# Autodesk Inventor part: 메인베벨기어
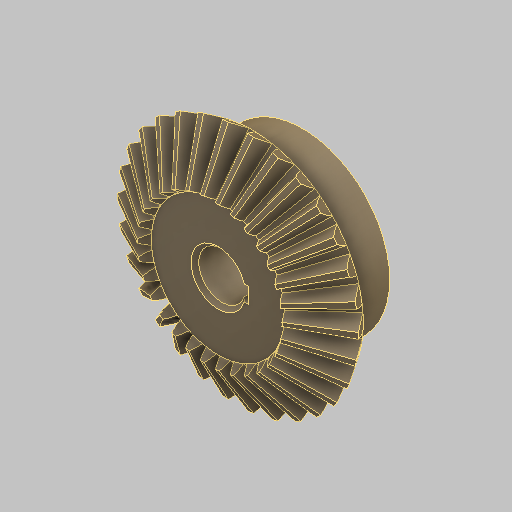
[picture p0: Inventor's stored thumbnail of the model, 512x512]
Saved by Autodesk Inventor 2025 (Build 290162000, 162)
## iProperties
Created: 2024-08
Part Number: 메인베벨기어
Material: 강철, 탄소
Document SubType Name: Modeling
Designer: 현기
Density: 7.87 g/cm^3
Appearance: 기본값
Author: jhkim
Sending System: Autodesk Inventor 2025
Preprocessor: ST-DEVELOPER v20
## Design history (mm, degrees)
feature "Solid1"
node "솔리드1"
